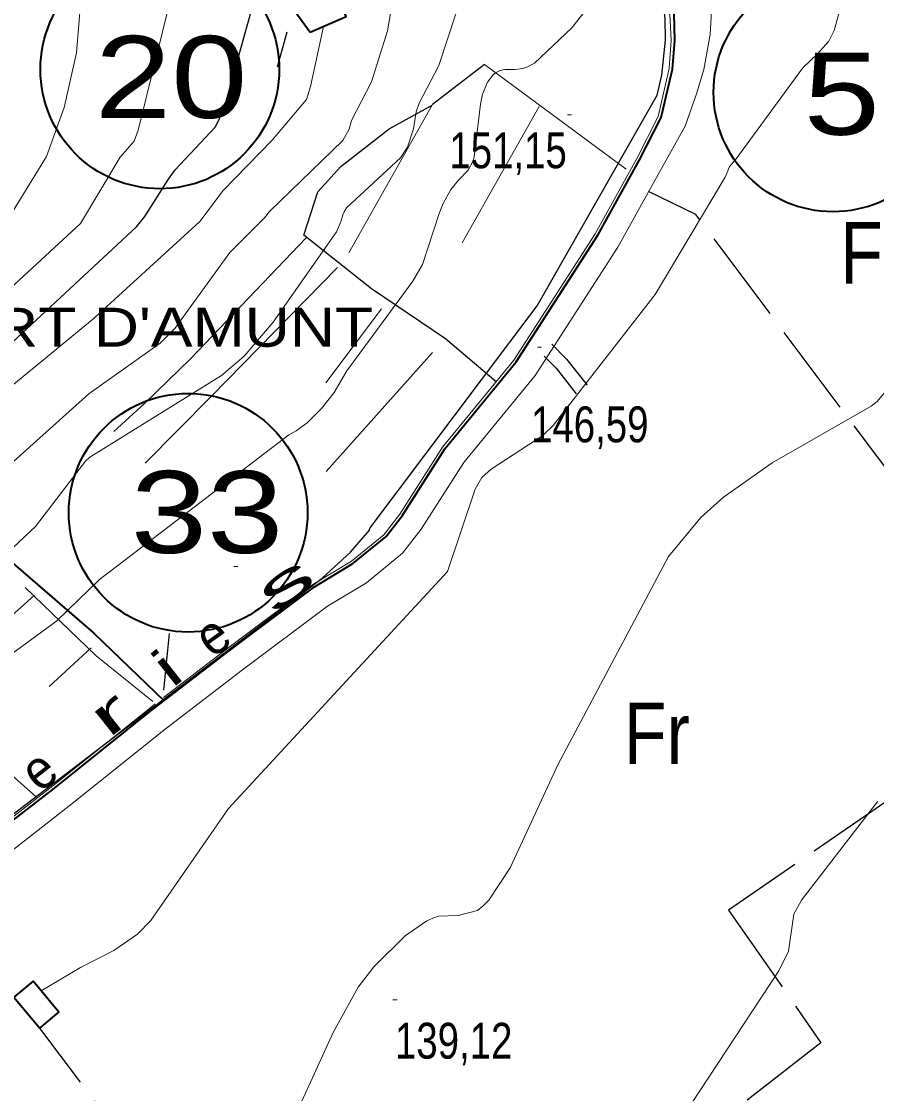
# Model space of a CAD drawing. Extents: x 483847 to 488453, y 4383581 to 4386795.
# Drawn here: x 485975 to 486183.5, y 4385624.3 to 4385885.8 of the extents above; entities that cross this region are included whole.
import ezdxf
from ezdxf.enums import TextEntityAlignment as Align

# ---------------------------------------------------------------- set-up
doc = ezdxf.new("R2010")
doc.units = 0
doc.header["$LTSCALE"] = 3.8
doc.linetypes.add('LONG_DASHED', pattern=[7.5, 6, -1.5])
doc.linetypes.add('MEDIUM_DASHED', pattern=[4.5, 3, -1.5])
for name, color, linetype, lineweight in [('13', 7, 'Continuous', 25), ('25', 7, 'LONG_DASHED', 25), ('38', 7, 'Continuous', 25), ('47', 7, 'Continuous', 35), ('51', 7, 'Continuous', 13), ('6', 7, 'Continuous', 35), ('7', 7, 'Continuous', 13), ('8', 7, 'Continuous', 25), ('9', 7, 'Continuous', 13)]:
    doc.layers.add(name, color=color, linetype=linetype, lineweight=lineweight)
doc.layers.add('31', color=7, linetype='Continuous')
doc.layers.add('5', color=7, linetype='Continuous')

msp = doc.modelspace()

# ---------------------------------------------------------------- linework, layer by layer
at = {"layer": '25'}
for p, q in [((486087.89, 4385875.31), (486075.22, 4385865.52)), ((486023.76, 4385581.6), (485979.51, 4385640.27))]:
    msp.add_line(p, q, dxfattribs=at)
for points in [[(486090.79, 4385797.95), (486078.38, 4385808.44), (486060.39, 4385820.56), (486043.85, 4385833.7), (486047.3, 4385844.23), (486052.87, 4385850.45), (486064.71, 4385859.59), (486075.14, 4385865.37)], [(486259.77, 4385829.04), (486191.72, 4385768.92), (486139.44, 4385838.71), (486127.9, 4385844.3)], [(485978.64, 4385696.71), (485944.32, 4385726.85), (485937.99, 4385729.79)], [(486228.74, 4385643.51), (486187.07, 4385696.36), (486147.44, 4385669.08), (486169.94, 4385636.72), (486134.27, 4385608.94), (486144.43, 4385594.84), (486145, 4385593.18), (486144.7, 4385592.96), (486111.58, 4385564.92), (486123.46, 4385545.24), (486116.3, 4385538.07), (486191.46, 4385442.15)]]:
    msp.add_lwpolyline(points, dxfattribs=at)
at = {"layer": '38'}
msp.add_lwpolyline([(486104.36, 4385807.13), (486107.93, 4385803.46), (486112.92, 4385797.09)], dxfattribs=at)
at = {"layer": '38', "linetype": 'MEDIUM_DASHED'}
msp.add_lwpolyline([(486102.46, 4385804.18), (486105.36, 4385801.21), (486110.24, 4385794.99)], dxfattribs=at)
at = {"layer": '47'}
for points in [[(486045.39, 4385883.2), (486054.22, 4385886.98), (486050.02, 4385896.78), (486043.46, 4385893.98), (486045.53, 4385889.1), (486042.2, 4385887.69)], [(485973.2, 4385647.8), (485979.51, 4385640.27), (485984.18, 4385644.19), (485977.87, 4385651.72)]]:
    msp.add_lwpolyline(points, close=True, dxfattribs=at)
at = {"layer": '51'}
for p, q in [((486122.49, 4385849.76), (486087.89, 4385875.31)), ((486075.22, 4385865.52), (486054.82, 4385829.34)), ((486101.25, 4385865.07), (486082.47, 4385831.8)), ((486062.8, 4385815.72), (486049.26, 4385797.68)), ((486075.25, 4385805.04), (486049.33, 4385776.07)), ((485978.21, 4385745.87), (485967.11, 4385735.9)), ((485992.06, 4385733.07), (485981.79, 4385723.61))]:
    msp.add_line(p, q, dxfattribs=at)
for points in [[(486145.78, 4385914.78), (486143.61, 4385894.17), (486142.92, 4385882.63), (486141.37, 4385874.1), (486139.64, 4385868.12), (486136.82, 4385860.28)], [(486009.68, 4385720.9), (486025.06, 4385732.7), (486046.11, 4385748.5), (486055.47, 4385754.14), (486063.38, 4385760.56), (486067.31, 4385765.66), (486077.7, 4385781.94), (486095.1, 4385803.23), (486114.93, 4385834.02), (486124.99, 4385852.21), (486130.29, 4385862.61), (486132.93, 4385874.31), (486133.39, 4385881.21), (486133.12, 4385887.51), (486132.93, 4385888.52), (486128.46, 4385900.02)], [(485905.13, 4385622.48), (485917.81, 4385634.81), (485933.63, 4385650.03), (485950.93, 4385666.7), (485966.34, 4385678.67), (485986.62, 4385694.39), (486010.09, 4385713.19), (486028.9, 4385727.64), (486049.67, 4385743.22), (486059.14, 4385748.91), (486067.94, 4385756.11), (486072.52, 4385761.98), (486082.86, 4385778.22), (486100.25, 4385799.49), (486120.4, 4385830.74), (486130.63, 4385849.22), (486136.89, 4385860.45)], [(486044.44, 4385833.02), (486016.25, 4385803.56), (486005.07, 4385792.61), (485997.54, 4385785.81)], [(486052.06, 4385825.78), (486021.3, 4385794.33), (486005.16, 4385778.05)], [(485975.91, 4385747.78), (485993.23, 4385731.1), (486007.08, 4385719.98)], [(485951.16, 4385674.92), (485962.45, 4385683.7), (485982.69, 4385699.39), (486006.15, 4385718.19), (486007.67, 4385719.36)]]:
    msp.add_lwpolyline(points, dxfattribs=at)
at = {"layer": '6', "lineweight": 25}
for p, q in [((486037.45, 4385874.71), (486039.81, 4385883.27)), ((486011.03, 4385736.5), (486009.7, 4385722.74))]:
    msp.add_line(p, q, dxfattribs=at)
at = {"layer": '6'}
for points in [[(485890.29, 4385615.9), (485901.17, 4385626.54), (485913.87, 4385638.89), (485929.7, 4385654.12), (485947.21, 4385671), (485962.86, 4385683.17), (485983.11, 4385698.85), (486006.57, 4385717.65), (486025.47, 4385732.16), (486046.49, 4385747.94), (486055.86, 4385753.58), (486063.86, 4385760.09), (486067.88, 4385765.26), (486078.26, 4385781.54), (486095.66, 4385802.83), (486115.53, 4385833.66), (486125.62, 4385851.88), (486131, 4385862.35), (486133.77, 4385874.18), (486134.33, 4385881.18), (486134.19, 4385887.6)], [(485932.11, 4385782.21), (485933.32, 4385782.91), (485934.79, 4385783.22), (485937.94, 4385783.17), (485939.15, 4385783.07), (485940.12, 4385782.7), (485942.48, 4385780.51), (485965.14, 4385760.38), (485992.65, 4385736.64), (486009.82, 4385720.15)]]:
    msp.add_lwpolyline(points, dxfattribs=at)
for centre in [(486008.78, 4385874.11), (486172.87, 4385868.5), (486015.67, 4385765.99)]:
    msp.add_circle(centre, 29.1, dxfattribs=at)
at = {"layer": '7'}
for p, q in [((486108.15, 4385863.01), (486109.15, 4385863.01)), ((486100.81, 4385806.39), (486101.81, 4385806.39)), ((486026.81, 4385752.9), (486027.81, 4385752.9)), ((486065.59, 4385647.21), (486066.59, 4385647.21))]:
    msp.add_line(p, q, dxfattribs=at)
at = {"layer": '8'}
for points in [[(485855.38, 4385576.01), (485855.92, 4385576.92), (485856.6, 4385577.83), (485888.17, 4385606.31), (485888.35, 4385606.44), (485888.46, 4385606.57), (485898.34, 4385623.32), (485949.3, 4385674.4), (486048.34, 4385750.06), (486055.23, 4385756.36), (486059.85, 4385761.75), (486059.97, 4385762.12), (486060.06, 4385762.29), (486100.73, 4385816.48), (486130.05, 4385867.8), (486131.13, 4385872.71), (486132.05, 4385881.26), (486131.98, 4385886.63), (486131.63, 4385889.16), (486128.72, 4385897.2), (486128.33, 4385898.98), (486128.13, 4385900.56), (486126.91, 4385905.82), (486125.97, 4385907.86)], [(485699.83, 4385621.78), (485739.98, 4385624.41), (485741.64, 4385625.06), (485742.43, 4385625.49), (485774.69, 4385650.42), (485777.59, 4385654.05), (485779.12, 4385656.47), (485780.8, 4385657.94), (485785.34, 4385660.84), (485862.29, 4385722.55), (485880.2, 4385733.04), (485881.03, 4385733.58), (485883.63, 4385736.01), (485884.24, 4385736.42), (485888.17, 4385738.56), (485922.96, 4385761.24), (486003.11, 4385835.73), (486005.13, 4385838.21), (486010.86, 4385847.36), (486012.52, 4385849.6), (486022.33, 4385860.14), (486024.38, 4385864.32), (486033.41, 4385896.81)]]:
    msp.add_lwpolyline(points, dxfattribs=at)
at = {"layer": '9'}
for points in [[(486061.37, 4385971.89), (486063.46, 4385962.4), (486063.75, 4385959.91), (486063.71, 4385940.96), (486066.72, 4385911.47), (486066.51, 4385896.88), (486064.26, 4385883.53), (486060.39, 4385871.1), (486055.46, 4385861.68), (486054.9, 4385859.53), (486053.38, 4385856.81), (486035.49, 4385839.45), (486034.29, 4385837.94), (486025.81, 4385829.46), (486012.42, 4385810.93), (486008.88, 4385807.36), (485991.43, 4385795.01), (485955.43, 4385762.69), (485951.54, 4385758.47), (485838.06, 4385668.59), (485789.41, 4385619.49)], [(485979.86, 4385649.35), (485989.45, 4385655.11), (485997.57, 4385659.26), (486003.3, 4385663.19), (486006.55, 4385666.56), (486025.55, 4385693.82), (486078.89, 4385751.69), (486085.68, 4385771.75), (486087.24, 4385774.56), (486089.57, 4385776.65), (486102.11, 4385784.83), (486104.68, 4385787.24), (486129.54, 4385819.21), (486146.57, 4385847.85), (486147.66, 4385850.34), (486148.13, 4385851.01), (486149.29, 4385852.27), (486165.49, 4385874.51), (486169.1, 4385877.88), (486171.89, 4385881.03), (486173.14, 4385883.61), (486174.84, 4385889.79), (486176.08, 4385898.15), (486174.81, 4385921.75)], [(485970.64, 4385835.77), (485981.16, 4385852.87), (485985.43, 4385864.85), (485988.45, 4385878.19), (485991.01, 4385908.81)], [(486082.97, 4385893.94), (486076.75, 4385875.07), (486071.98, 4385865.89), (486071.27, 4385863.77), (486070.59, 4385859.63), (486069.18, 4385855.16), (486067.44, 4385852.58), (486054.25, 4385840.37), (486053.68, 4385839.37), (486053.39, 4385838.62), (486052.92, 4385836.92), (486051.85, 4385834.51), (486036.41, 4385812.48), (486029.34, 4385804.15), (486023.82, 4385799.48), (485991.74, 4385779.55), (485990.64, 4385778.56), (485978.42, 4385762.6), (485951.06, 4385736.97), (485875.62, 4385679.4), (485862.53, 4385665.98), (485851.31, 4385652.22), (485834.1, 4385636.69), (485791.07, 4385596.74)], [(486011.48, 4385891.56), (486003.52, 4385859.29), (486002.49, 4385856.63), (485999.06, 4385852.71), (485989.44, 4385836.54), (485903.89, 4385757.48)], [(486113.13, 4385889.25), (486109.18, 4385884.24), (486100.09, 4385875.65), (486098.27, 4385874.64), (486097.24, 4385874.31), (486095.37, 4385874.12), (486092.86, 4385874.07), (486091.7, 4385873.88), (486090.63, 4385873.3), (486089.97, 4385872.68), (486088.66, 4385871.04), (486087.45, 4385868.11), (486086.94, 4385865.66), (486085.39, 4385852.8), (486085.12, 4385851.78), (486083.97, 4385849.55), (486081.6, 4385847.11), (486079.74, 4385844.79), (486077.85, 4385841.44), (486076.9, 4385838.95), (486072.79, 4385826.54), (486070.48, 4385822.43), (486054.37, 4385800.57), (486051.25, 4385795.31), (486048.22, 4385791.4), (486044.65, 4385787.93), (486041.98, 4385785.96), (486040.2, 4385784.98), (485994.07, 4385749.73), (485983.69, 4385739.63), (485966.2, 4385726.87)], [(485683.57, 4385579.92), (485692.89, 4385593.06), (485693.14, 4385593.41), (485693.61, 4385593.91), (485747.73, 4385612.82), (485758.44, 4385618.73), (485774.7, 4385631.33), (485793.6, 4385649.76), (485992.75, 4385813.46), (485992.86, 4385813.55), (485992.92, 4385813.6), (485993.01, 4385813.72), (486018.5, 4385837), (486024.19, 4385844.59), (486036.16, 4385856.89), (486044.49, 4385866.81), (486045.52, 4385869.91), (486048.65, 4385884.6)], [(486038.77, 4385612.29), (486051.04, 4385639.22), (486057.12, 4385650.3), (486060.97, 4385655.2), (486068.56, 4385662.76), (486073.89, 4385666.48), (486075.31, 4385667.11), (486076.69, 4385667.57), (486081.46, 4385667.78), (486086.21, 4385669), (486087.58, 4385670.09), (486088.97, 4385671.51), (486094.19, 4385679.35), (486105.9, 4385704.63), (486132.74, 4385755.35), (486140.69, 4385764.81), (486146.17, 4385769.75), (486158.01, 4385778.15), (486182.22, 4385791.99), (486183.64, 4385793.12), (486205.88, 4385819.99), (486225.42, 4385838.22)], [(486183.78, 4385695.57), (486183.29, 4385695.01), (486165.23, 4385671.51), (486163.36, 4385668.07), (486162.02, 4385659.07), (486159.64, 4385654.3), (486138.41, 4385621.89)]]:
    msp.add_lwpolyline(points, dxfattribs=at)

# ---------------------------------------------------------------- texts
at = {"layer": '13', "width": 1.25}
for s, p in [('20', (486011.53, 4385862.27)), ('5', (486175.03, 4385858.18)), ('33', (486020.27, 4385756.17))]:
    msp.add_text(s, height=20, dxfattribs=at).set_placement(p, align=Align.CENTER)
at = {"layer": '31', "width": 0.85}
for p in [(486182.67, 4385821.89), (486129.95, 4385704.69)]:
    msp.add_text('Fr', height=15, dxfattribs=at).set_placement(p, align=Align.CENTER)
at = {"layer": '5', "width": 1.2}
msp.add_text("SORT D'AMUNT", height=9.5, dxfattribs=at).set_placement((486060.78, 4385806.48), align=Align.RIGHT)
at = {"layer": '5'}
for s, rotation, width, p in [('s', 35.543, 2.15, (486041.96, 4385744.93)), ('e', 35.543, 0.95, (486024.26, 4385732.29)), ('i', 38.386, 1.6, (486013.43, 4385724.38)), ('r', 38.386, 2.05, (485999.49, 4385713.34)), ('e', 38.386, 0.95, (485982.12, 4385699.58))]:
    msp.add_text(s, height=9.49, rotation=rotation, dxfattribs=dict(at, width=width)).set_placement(p, align=Align.CENTER)
at = {"layer": '7', "width": 0.8}
for s, p in [('151,15', (486079.35, 4385850)), ('146,59', (486099.27, 4385783.16)), ('139,12', (486066.09, 4385632.84))]:
    msp.add_text(s, height=8.75, dxfattribs=at).set_placement(p)

doc.saveas('drawing.dxf')
